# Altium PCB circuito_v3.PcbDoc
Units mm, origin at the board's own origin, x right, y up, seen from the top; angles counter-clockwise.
Board outline 66.93 x 40.77 mm, 2 copper layers (Top Layer, Bottom Layer); 47 components, 32 nets, 112 pads, 55 vias.
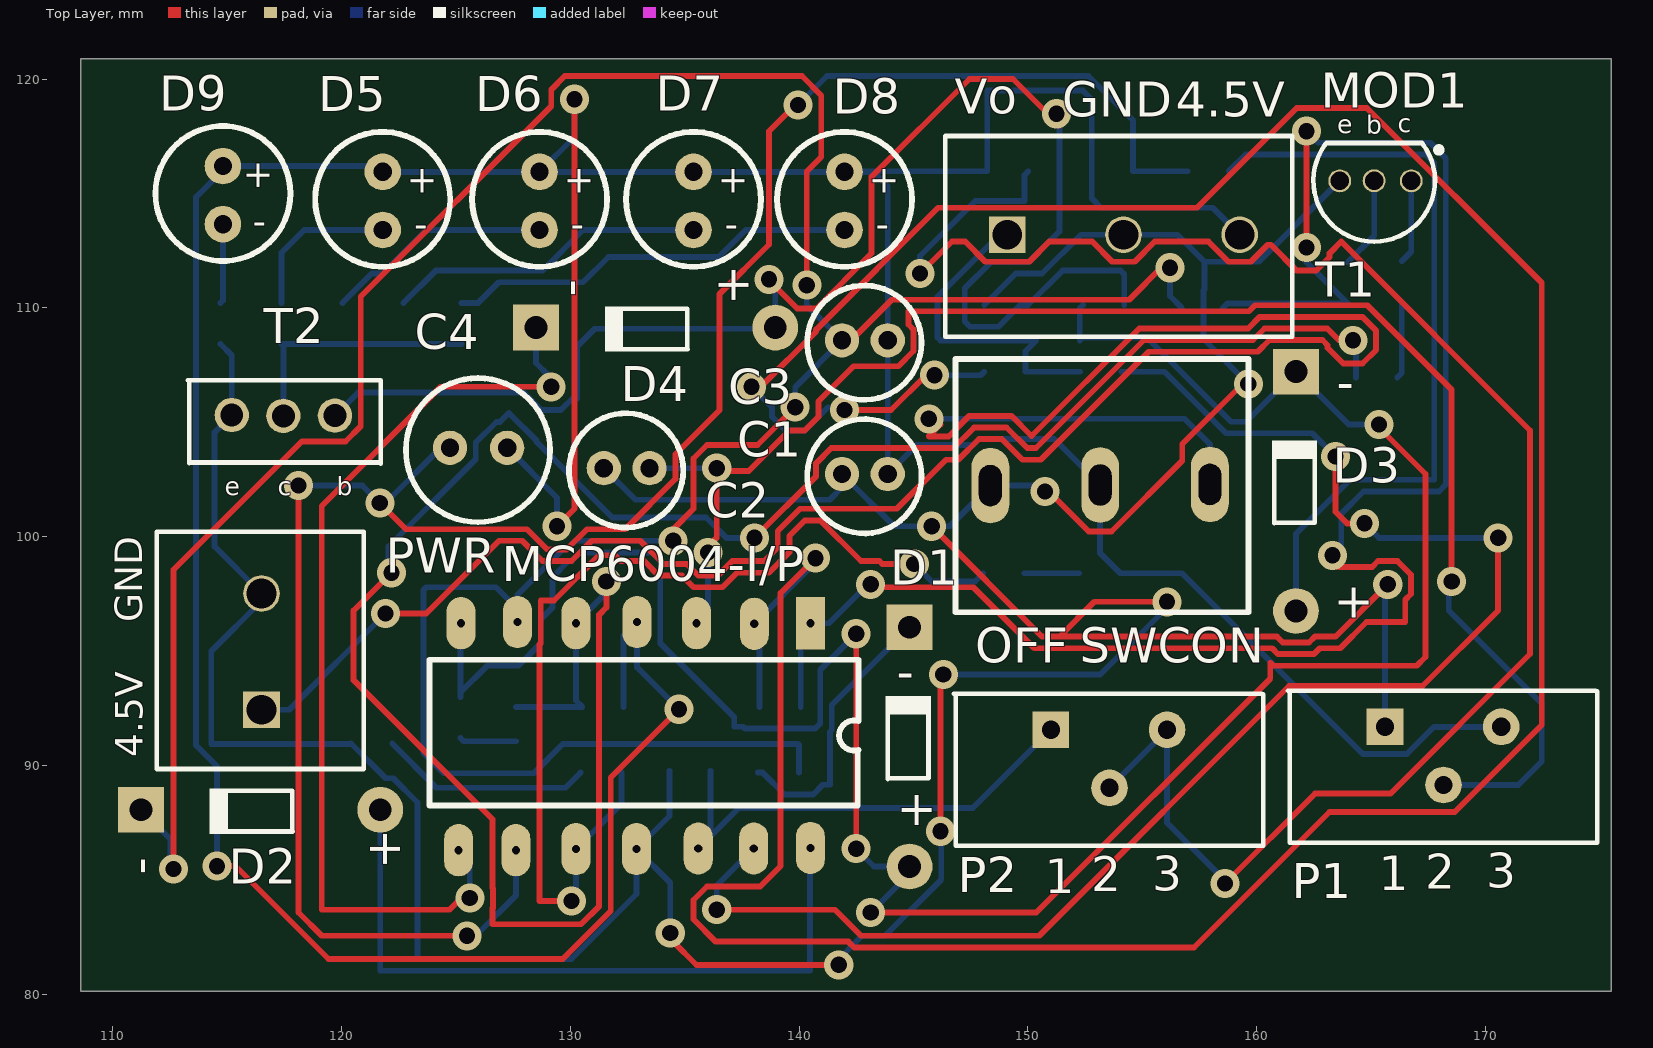
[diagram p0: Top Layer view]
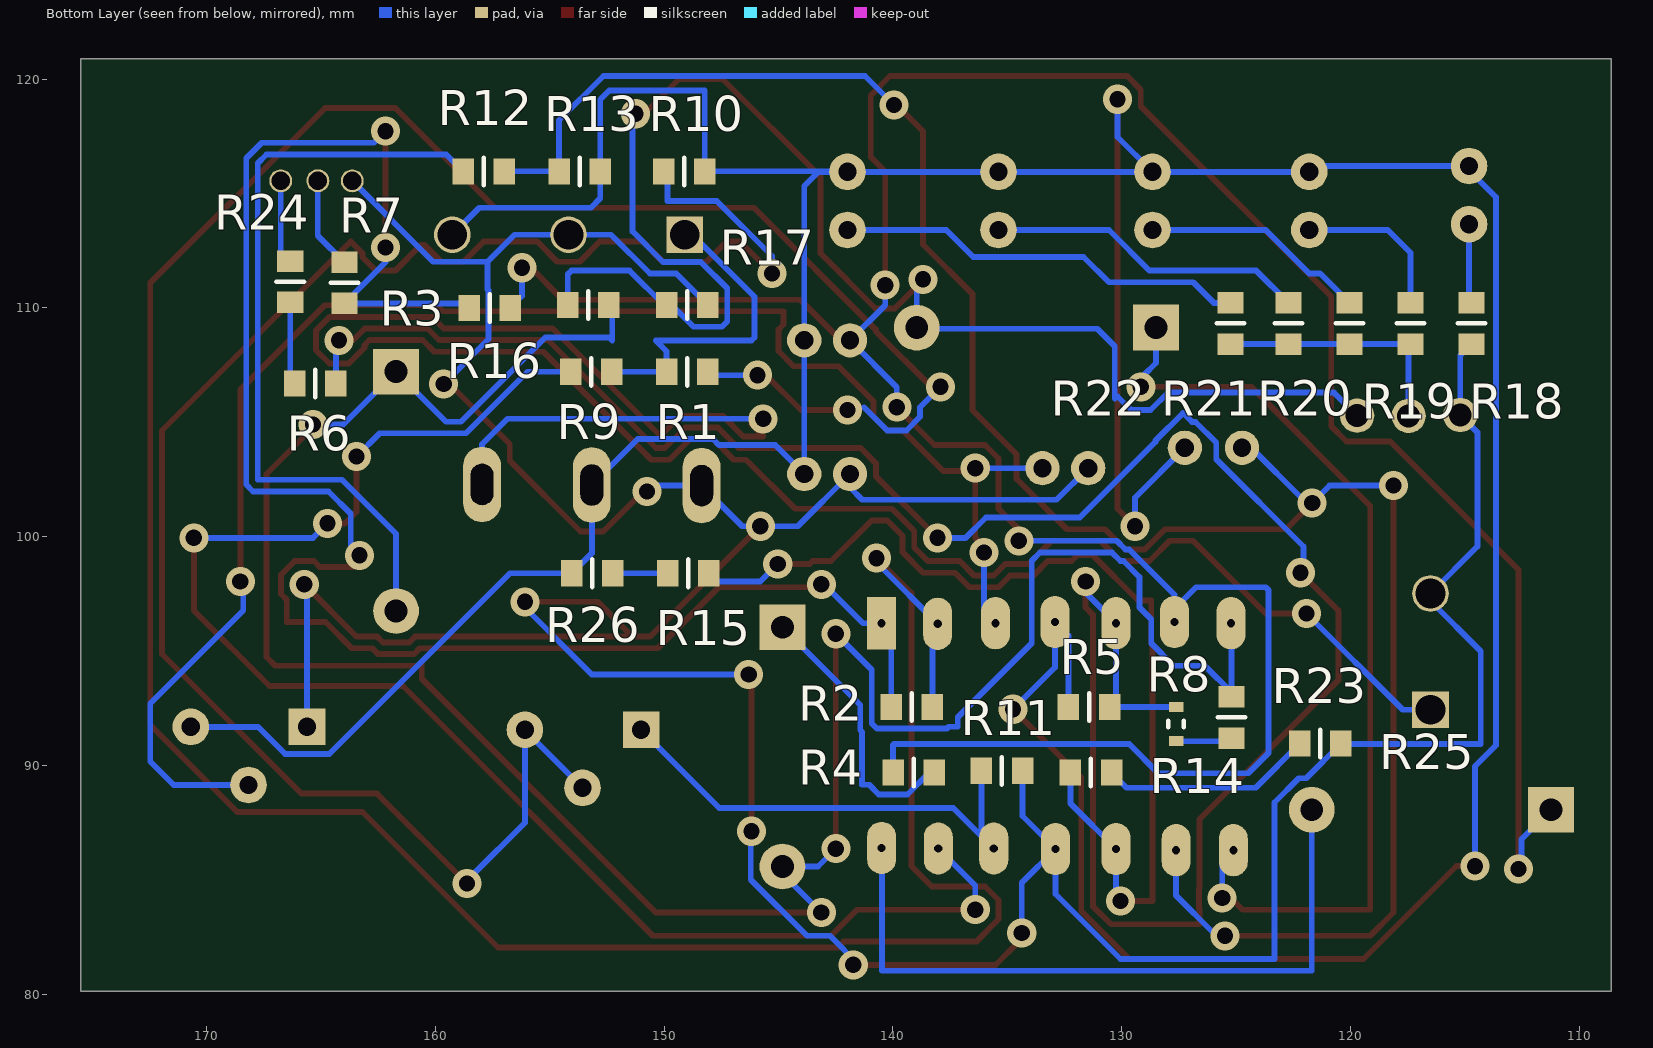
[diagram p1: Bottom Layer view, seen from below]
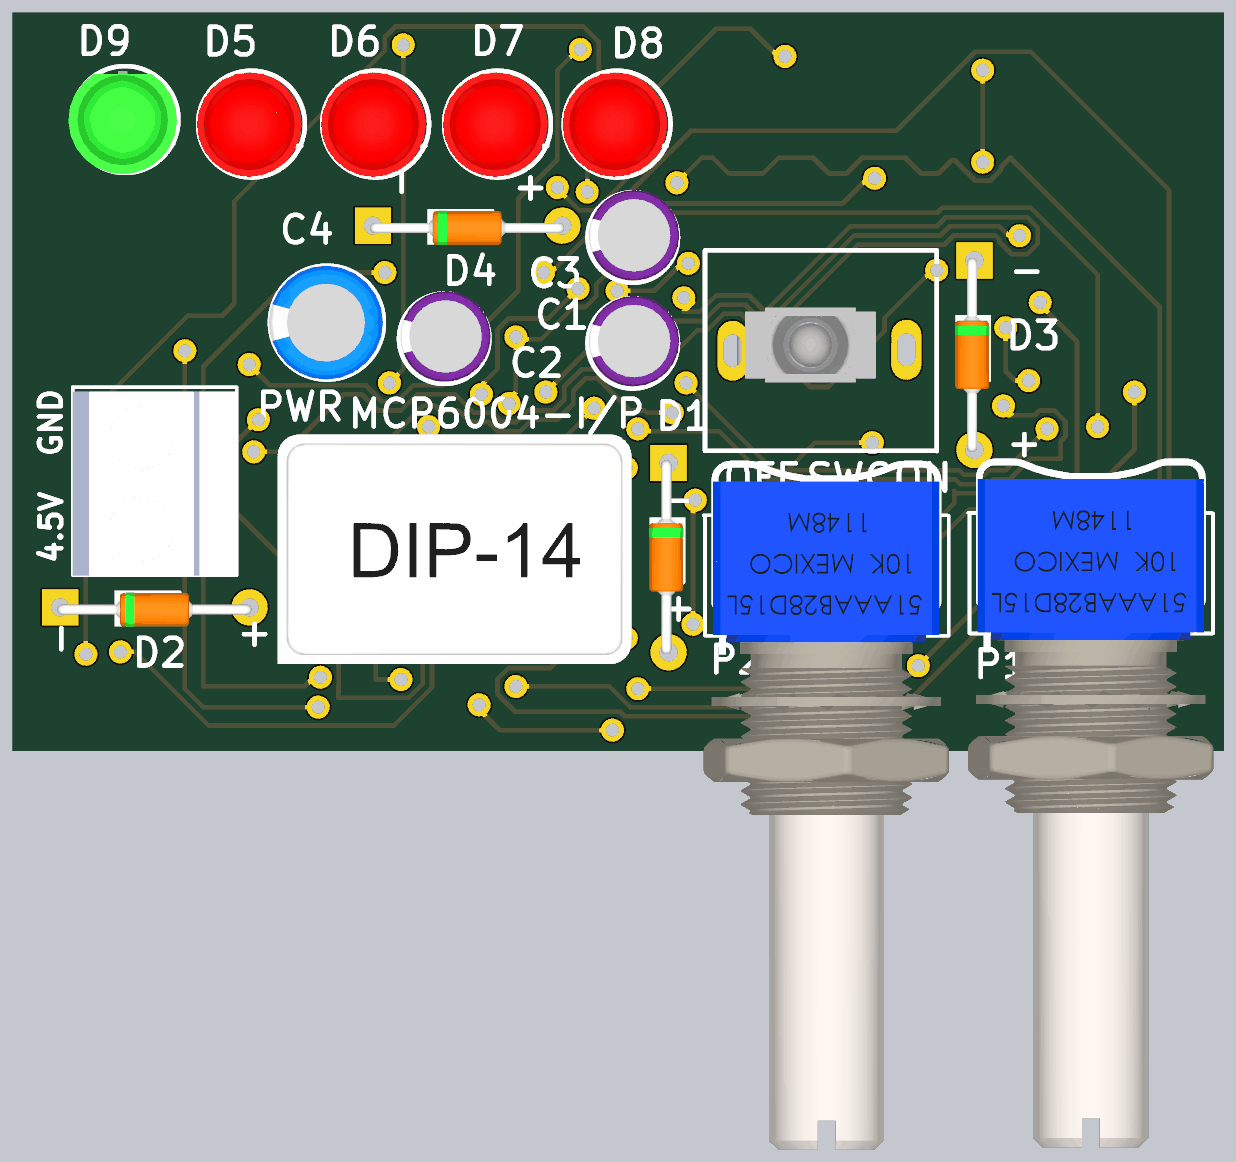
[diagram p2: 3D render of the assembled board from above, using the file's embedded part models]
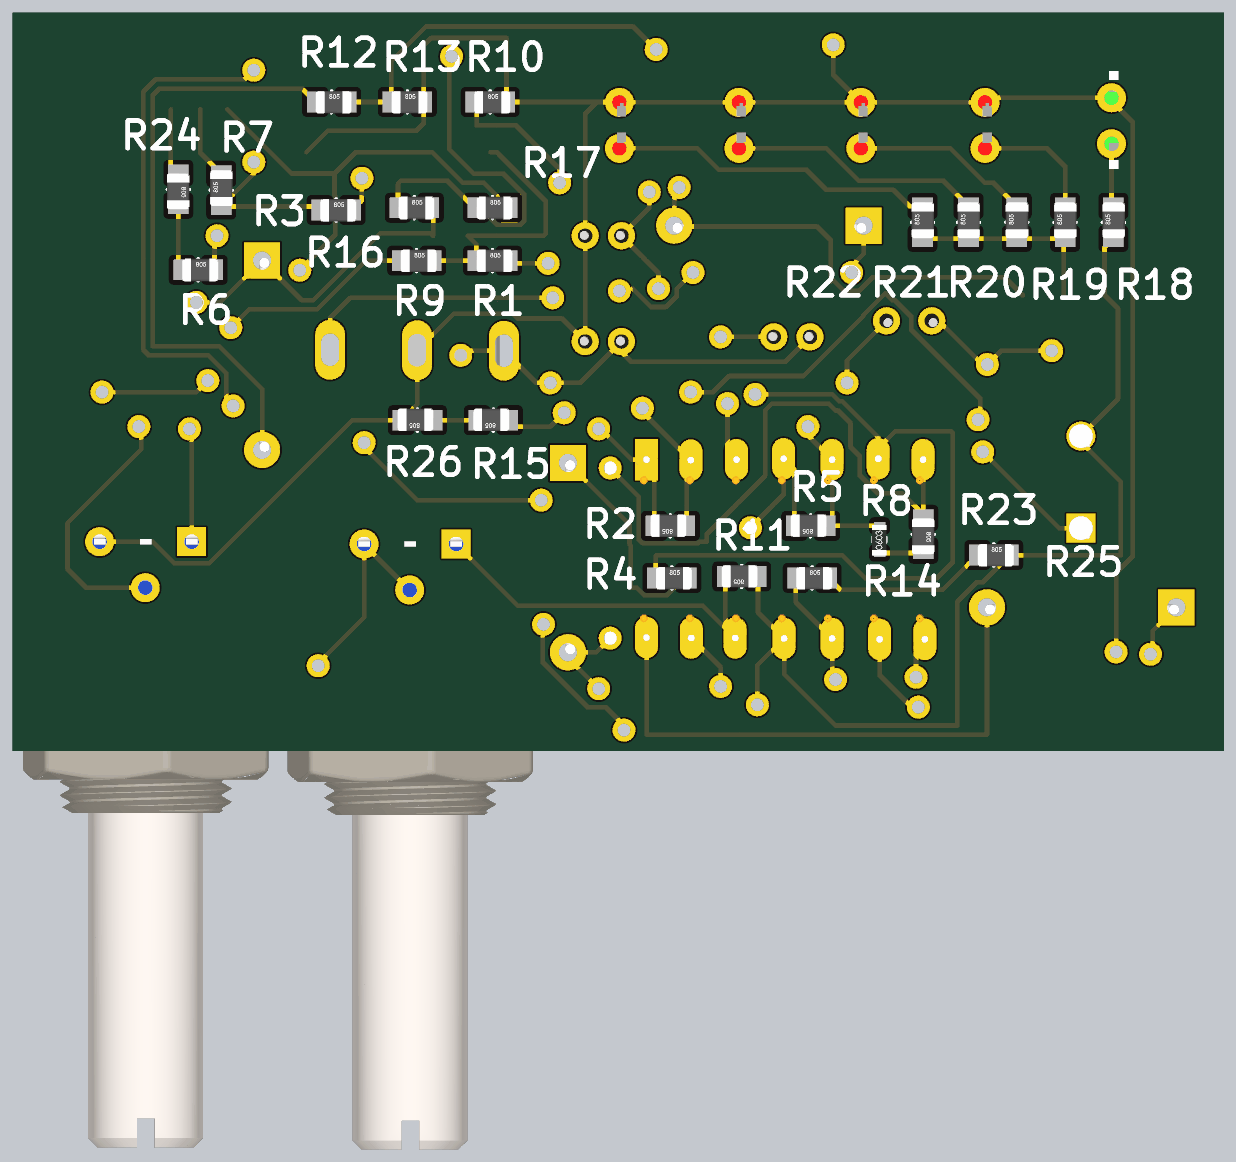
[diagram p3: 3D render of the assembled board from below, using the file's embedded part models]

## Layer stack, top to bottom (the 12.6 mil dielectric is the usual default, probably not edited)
Top Layer: signal copper 0.0356
Dielectric: dielectric 0.32, FR-4, Dk 4.8
Bottom Layer: signal copper 0.0356

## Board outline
108.585,80.137 175.514,80.137 175.514,120.904 108.585,120.904

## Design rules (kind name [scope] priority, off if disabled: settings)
Clearance Clearance_Vias_a_Mano [IsComponentBody vs IsVia] p1: gap=1.524
Clearance [All] p2: gap=0.254
MinimumSolderMaskSliver SilkscreenOverComponentPads [All] p2: minsoldermaskwidth=0.254
PolygonConnect [All] p1: connectstyle=Relief reliefconductorwidth=0.254 reliefentries=4 polygonreliefangle="90 Angle" airgapwidth=0.254
RoutingLayers RoutingLayers_1 [InNet('GND')] p1: top layer_v5=FALSE bottom layer_v5=FALSE
RoutingLayers [All] p2: top layer_v5=TRUE bottom layer_v5=TRUE
RoutingPriority RoutingPriority_GND [InNet('GND')] p1: routingpriority=0
RoutingPriority [All] p2: routingpriority=100
RoutingVias RoutingVias_A_Mano [All] p1: holewidth=0.889 width=2.032 viastyle="Through Hole" minholewidth=0.889 minwidth=1.778 maxholewidth=0.889 maxwidth=2.54
SolderMaskExpansion [All] p1: expansion=0.102
Width Width_Vcc [(InNet('VCC+') AND InNet('VCC-'))] p1: maxlimit=5.08 minlimit=1.778 preferedwidth=2.032
Width [All] p2: maxlimit=2.54 minlimit=0.254 preferedwidth=0.508
26 further rules are at their usual default settings.

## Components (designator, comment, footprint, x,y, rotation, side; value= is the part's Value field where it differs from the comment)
C1 "Cap" "Condensador 5mm" 142.875,102.743 r0 top
C2 "Cap" "Condensador 5mm" 132.461,102.997 r0 top
C3 "Cap" "Condensador 5mm" 142.875,108.585 r0 top
C4 "Cap" "Condensador 6.3mm" 125.984,103.886 r0 top
D1 "BAT85" BAT85 144.78,90.932 r0 top
D2 "Diode BAT18" BAT85 116.332,88.011 r90 top
D3 "Diode BAT18" BAT85 161.671,102.108 r0 top
D4 "Diode BAT18" BAT85 133.604,109.093 r90 top
D5 "LED" LED 121.793,115.951 r270 top
D6 "LED" LED 128.651,115.951 r270 top
D7 "LED" LED 135.382,115.951 r270 top
D8 "LED" LED 141.986,115.951 r270 top
D9 "LED" "LED verde" 114.808,116.205 r270 top
MCP6004-I/P "MCP6004-I/P" MCP6004 139.065,96.393 r270 top
MOD1 "Conector" Conector 185.293,104.394 r270 top
P1 "Res Tap" POTENCIOMETRO 168.148,91.694 r270 top
P2 "Res Tap" POTENCIOMETRO 153.543,91.567 r270 top
PWR "Header 2" ALM 133.096,105.918 r90 top
R1 "Res1" "SMD 0805" 155.956,109.347 r180 bottom
R2 "Res1" "SMD 0805" 132.207,90.424 r0 bottom
R3 "Res1" "SMD 0805" 164.592,112.141 r180 bottom
R4 "Res1" "SMD 0805" 146.05,91.821 r180 bottom
R5 "Res1" "SMD 0805" 124.46,90.424 r0 bottom
R6 "Res1" "SMD 0805" 172.212,108.839 r180 bottom
R7 "Res1" "SMD 0805" 166.116,104.14 r90 bottom
R8 "Res1" "SMD 0603" 127.635,91.821 r180 bottom
R9 "Res1" "SMD 0805" 160.147,109.347 r180 bottom
R10 "Res1" "SMD 0805" 156.083,118.11 r180 bottom
R11 "Res1" "SMD 0805" 128.27,87.63 r0 bottom
R12 "Res1" "SMD 0805" 164.846,118.11 r180 bottom
R13 "Res1" "SMD 0805" 160.655,118.11 r180 bottom
R14 "Res1" "SMD 0805" 138.303,91.821 r180 bottom
R15 "Res1" "SMD 0805" 141.986,96.266 r0 bottom
R16 "Res1" "SMD 0805" 160.274,112.268 r180 bottom
R17 "Res1" "SMD 0805" 155.956,112.268 r180 bottom
R18 "Res3" "SMD 0805" 116.84,102.362 r90 bottom
R19 "Res3" "SMD 0805" 119.507,102.362 r90 bottom
R20 "Res3" "SMD 0805" 122.174,102.362 r90 bottom
R21 "Res3" "SMD 0805" 124.841,102.362 r90 bottom
R22 "Res3" "SMD 0805" 127.381,102.362 r90 bottom
R23 "Res1" "SMD 0805" 123.063,99.06 r270 bottom
R24 "Resistencia" "SMD 0805" 164.211,118.11 r270 bottom
R25 "Resistencia" "SMD 0805" 128.27,93.091 r180 bottom
R26 "Resistencia" "SMD 0805" 146.177,96.266 r0 bottom
SWC "Switch" switch 150.368,101.6 r0 top
T1 "2N3904" "T1 BC550C" 154.813,175.133 r90 top
T2 "QNPN" "T2 BD139" 108.204,40.894 r270 top

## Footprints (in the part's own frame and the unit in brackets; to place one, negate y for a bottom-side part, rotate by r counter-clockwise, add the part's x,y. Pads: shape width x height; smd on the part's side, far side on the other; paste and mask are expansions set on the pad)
ALM [mm]
  rect 1.6x1.6 hole 1.3: 1(-13.48,16.6)
  round 1.6 hole 1.3: 2(-8.4,16.6)
  silkscreen extent -16.07,12.12 -5.7,21.17, body extent -16.1,12.18 -4.94,21.17, height 15.2
BAT85 [mm]
  round 2 hole 1: 1(0.049,-5.353)
  rect 2x2 hole 1: 2(0.049,5.107)
  silkscreen extent -1,-1.53 0.97,2.1, body extent -1.02,-5.46 0.88,5.26, height 1.95
"Condensador 5mm" [mm]
  round 1.5 hole 0.8: 1(-1,0) 2(1,0)
  silkscreen extent -2.52,-2.6 2.47,2.4, body extent -2.45,-2.47 2.55,2.52, height 11
"Condensador 6.3mm" [mm]
  round 1.5 hole 0.8: 1(-1.25,0) 2(1.25,0)
  silkscreen extent -3.17,-3.25 3.12,3.05, body extent -3.22,-3.25 3.08,3.05, height 11.5
Conector [mm]
  rect 1.6x1.6 hole 1.3: 1(-8.811,-36.193)
  round 1.6 hole 1.3: 2(-8.811,-31.113) 3(-8.811,-26.033)
  silkscreen extent -13.13,-38.9 -4.35,-23.72, body extent -13.25,-38.87 -4.25,-23.63, height 15.2
LED [mm]
  round 1.6 hole 0.8: 1(0,0) 2(2.54,0)
  silkscreen extent -1.75,-2.95 4.15,2.95, body extent -1.68,-3.03 4.12,2.77, height 17.5
"LED verde" [mm]
  round 1.6 hole 0.8: 1(0,0) 2(2.54,0)
  silkscreen extent -1.75,-2.95 4.15,2.95, body extent -1.47,-3.12 4.23,2.87, height 20.86
MCP6004 [mm]
  rect 2.286x1.27 hole 0.356: 1(0.175,1.425)
  oval 2.286x1.27 hole 0.356: 2(0.2,-1.025) 3(0.175,-3.55) 4(0.125,-6.15) 5(0.175,-8.825) 6(0.125,-11.375) 7(0.175,-13.85) 8(10.1,-13.95) 9(10.1,-11.45) 10(10.05,-8.825) 11(10.05,-6.175) 12(10.025,-3.475) 13(10.025,-1.05) 14(10,1.425)
  silkscreen extent 1.78,-15.22 8.15,3.52, body extent -1.22,-15.84 11.48,3.72, height 4.61
POTENCIOMETRO [mm]
  rect 1.6x1.6 hole 0.8: 1(0.008,-2.535)
  round 1.6 hole 0.8: 2(2.548,0.025) 3(0.008,2.545)
  silkscreen extent -1.58,-6.78 5.07,6.75, body extent -4.59,-6.77 33.45,6.77, height 14.1
"SMD 0603" [mm]
  rect 0.64x0.44 smd mask+0.26: 1(0.018,-0.76) 2(0.018,0.74)
  silkscreen extent -0.33,-0.15 0.35,0.13, body extent -0.4,-0.9 0.4,0.8, height 0.56
"SMD 0805" [mm]
  rect 0.94x1.14 smd mask+0.26: 1(6.062,-2.136) 2(7.862,-2.136)
  silkscreen extent 6.96,-2.74 6.96,-1.54, body extent 6.08,-2.77 8.08,-1.52, height 0.78
switch [mil]
  oval 65x130 hole 39.37 slot 70.87 at 90 deg: 1(-79,25) 2(109.96,26) 3(298.94,27)
  silkscreen extent -139,-193 365,243, body extent -69,-61 250,136, height 720
"T1 BC550C" [mm]
  round 1 hole 0.8: 1(-59.575,-11.95) 2(-59.571,-10.328) 3(-59.575,-8.825)
  silkscreen extent -62.23,-13.28 -57.92,-7.67, body extent -61.73,-12.63 -58.1,-7.87, height 4.92
"T2 BD139" [mm]
  round 1.5 hole 1: 1(-64.425,6.992) 2(-64.389,9.246) 3(-64.4,11.5)
  silkscreen extent -65.95,5.07 -62.3,13.5, body extent -65.4,5.4 -62.7,13.2, height 13.6

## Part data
C1 C2 C3 C4: "Capacitor"
D1: library part "Diode BAT18", "Low-Loss RF Switching Diode"
D2 D3 D4: "Low-Loss RF Switching Diode"
D5 D6 D7 D8 D9: library part LED2, "Typical RED, GREEN, YELLOW, AMBER GaAs LED"
MCP6004-I/P: "DIP Switch, 7 Position, SPST"
MOD1: library part "Header 3", "Header, 3-Pin"
P1 P2: "Tapped Resistor"
PWR: "Header, 2-Pin"
R1 R2 R3 R4 R5 R6 R7 R8 R9 R10 R11 R12 R13 R14 R15 R16 R17 R18 R19 R20 R21 R22 R23 R24 R25 R26: "Resistor"
SWC: library part Conmutador
T1: "NPN General Purpose Amplifier"
T2: "NPN Bipolar Transistor"

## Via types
v1: diameter 1.27, hole 0.711, Top Layer to Bottom Layer, 55 vias

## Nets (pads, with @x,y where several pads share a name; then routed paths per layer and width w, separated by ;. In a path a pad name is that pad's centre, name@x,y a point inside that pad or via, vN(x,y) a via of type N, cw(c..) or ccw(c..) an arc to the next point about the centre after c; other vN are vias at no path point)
"4.5 V": C1.2 C3.2 C4.2 D5.1 D6.1 D7.1 D8.1 D9.1 MCP6004-I/P.4 MOD1.3 P1.3 R5.2 R10.2 R13.2 R26.2 SWC.2 | length 200.1
  Top Layer w0.254: v1@114.427,85.598 v1(114.554,85.598) 115.36,85.598 119.424,81.534 129.663,81.534 131.764,83.635 131.764,89.473 v1(134.747,92.456) ; v1(129.413,100.457) 130.175,101.219 v1(130.175,119.126)
  Bottom Layer w0.254: v1(114.554,85.598) 114.554,89.96 113.627,90.887 113.627,114.846 114.808,116.027 D9.1 121.539,116.205 D5.1 D6.1 ; C4.2 129.413,101.707 v1(129.413,100.457) ; v1(130.175,119.126) 130.175,117.475 D6.1 ; R5.2 132.322,95.675 MCP6004-I/P.4 132.915,94.288 v1@134.493,92.71 ; MOD1.3 158.079,114.386 153.203,114.386 152.793,114.796 R13.2 152.793,119.114 152.4,119.507 148.221,119.507 R10.2 142.009,115.974 D8.1 ; P1.3 167.752,91.686 166.571,90.505 164.638,90.505 156.741,98.402 R26.2 153.161,99.28 SWC.2 151.154,104.267 147.862,104.267 147.608,104.013 145.145,104.013 C1.2 C3.2 143.875,115.332 143.256,115.951 D8.1 ; D6.1 D7.1 D8.1
GND: C1.1 C2.1 MCP6004-I/P.11 MOD1.2 P1.1 PWR.2 R11.1 R17.2 R18.1 R25.2 SWC.1 T1.3 T2.1 | length 185.9
  Top Layer w0.254: v1@134.493,82.296 135.509,81.28 v1(141.732,81.28) ; v1(145.796,100.457) 150.622,95.631 151.384,95.631 ; v1@146.05,86.741 146.177,86.868 v1(146.177,87.122) v1@146.177,93.853 ; v1(150.749,101.981) 150.909,101.981 152.661,100.228 153.661,100.228 156.754,103.322 156.754,104.049 v1@159.385,106.68 ; v1(156.083,97.155) 152.908,97.155 151.384,95.631 ; v1(165.735,97.917) 163.449,95.631 162.549,95.631 162.292,95.374 161.148,95.374 160.891,95.631 151.384,95.631
  Bottom Layer w0.254: R18.1 115.196,107.932 T2.1 114.446,104.569 114.446,99.568 PWR.2 116.496,97.192 114.3,94.996 114.3,90.932 120.385,90.932 R25.2 121.922,89.441 122.257,89.441 123.317,88.381 123.317,81.534 130.048,81.534 132.89,84.376 MCP6004-I/P.11 ; C2.1 132.842,101.616 141.335,101.616 141.875,102.156 C1.1 144.161,100.457 v1(145.796,100.457) 146.583,100.457 SWC.1 150.368,102.235 v1@150.495,102.108 ; R11.1 134.332,87.785 MCP6004-I/P.11 ; v1(134.366,82.677) 134.366,84.867 MCP6004-I/P.11 ; v1@141.478,81.28 142.748,82.55 143.753,82.55 146.21,85.007 146.21,87.089 v1(146.177,87.122) ; v1(146.304,93.98) 153.162,93.98 156.083,96.901 v1(156.083,97.155) ; R17.2 149.468,111.506 150.622,111.506 152.321,113.205 MOD1.2 156.543,113.205 157.724,112.024 ; v1(159.639,106.68) 157.679,108.64 157.679,110.778 157.724,110.823 157.724,112.024 ; T1.3 160.104,112.024 157.724,112.024 ; P1.1 v1@165.613,97.404
NetD1_3: D1.2 R4.2 | length 12.1
  Bottom Layer w0.254: R4.2 138.409,89.685 139.36,88.734 140.616,88.734 141.036,89.154 141.351,89.154 141.351,91.468 141.428,91.545 141.428,92.638 D1.2
NetD2_1: D2.1 MCP6004-I/P.14 | length 31.2
  Bottom Layer w0.254: D2.1 121.685,81.026 140.481,81.026 140.481,86.384 MCP6004-I/P.14
NetD3_1: D3.1 R12.1 | length 33.7
  Bottom Layer w0.254: R12.1 159.523,116.713 167.386,116.713 167.767,116.332 167.767,102.489 164.084,102.489 161.72,100.125 D3.1
NetD4_1: D4.1 R16.1 R17.1 T2.3 | length 65.7
  Top Layer w0.254: v1(138.684,111.252) 138.684,111.212 139.914,109.982 140.756,109.982 143.167,112.393 143.167,115.735 147.447,120.015 149.352,120.015 v1@151.384,117.983
  Bottom Layer w0.254: T2.3 120.709,106.299 127.976,106.299 128.738,105.537 129.58,105.537 130.175,106.132 130.215,106.132 130.302,106.045 130.302,108.331 131.064,109.093 138.908,109.093 D4.1 138.957,110.725 v1@138.684,110.998 ; 151.384,117.856 151.384,113.35 150.048,112.014 148.397,112.014 147.243,110.86 147.243,109.404 147.466,109.181 148.722,109.181 149.673,110.132 R17.1 150.01,110.132 151.511,111.633 154.051,111.633 154.212,111.472 R16.1
  other v1: 151.257,118.491
NetD5_2: D5.2 R19.2 | length 7
  Bottom Layer w0.254: R19.2 117.371,112.418 118.364,113.411 D5.2
NetD6_2: D6.2 R20.2 | length 9.9
  Bottom Layer w0.254: R20.2 121.32,111.506 121.793,111.506 123.698,113.411 D6.2
NetD7_2: D7.2 R21.2 | length 14
  Bottom Layer w0.254: R21.2 124.114,111.633 128.778,111.633 130.556,113.411 D7.2
NetD8_2: D8.2 R22.2 | length 18.1
  Bottom Layer w0.254: R22.2 125.972,110.224 126.873,111.125 130.556,111.125 131.661,112.23 136.487,112.23 137.668,113.411 D8.2
NetD9_2: D9.2 R18.2 | length 3.5
  Bottom Layer w0.254: R18.2 114.808,110.328 D9.2
NetMOD1_1: MOD1.1 R1.1 R9.2 | length 14.3
  Bottom Layer w0.254: MOD1.1 148.765,113.205 146.05,110.49 146.05,108.712 146.177,108.585 150.368,108.585 149.894,108.111 R1.1 R9.2
NetP2_1: P2.2 P2.3 R10.1 | length 79.7
  Top Layer w0.254: v1(145.288,111.506) 146.685,112.903 147.263,112.903 148.142,112.024 150.058,112.024 150.937,112.903 152.812,112.903 153.691,112.024 154.669,112.024 155.548,112.903 157.892,112.903 158.771,112.024 159.749,112.024 160.487,112.762 160.63,112.762 161.758,111.633 162.6,111.633 163.195,112.228 163.195,112.395 163.703,112.903 171.958,104.648 171.958,94.869 165.862,88.773 162.56,88.773 v1(158.623,84.836)
  Bottom Layer w0.254: v1(145.288,111.506) 145.288,112.268 147.701,114.681 149.86,114.681 149.86,115.813 R10.1 ; P2.2 P2.3@156.088,91.539 ; P2.3 P2.3@156.088,91.539 ; v1@158.369,85.217 156.088,87.498 P2.3@156.088,91.539
NetPWR_1: PWR.1 SWC.3 | length 98.1
  Top Layer w0.254: v1(121.92,96.647) 123.699,96.647 126.874,99.822 127.893,99.822 128.782,98.933 130.044,98.933 130.933,99.822 133.056,99.822 134.072,98.806 135.088,98.806 135.596,98.298 136.438,98.298 137.073,98.933 138.47,98.933 139.065,99.528 139.065,100.247 140.037,101.219 144.272,101.219 146.419,103.366 146.961,103.366 147.862,104.267 148.861,104.267 149.762,103.366 150.566,103.366 155.288,108.088 160.054,108.088 160.562,108.596 162.878,108.596 163.101,108.373 163.101,108.258 163.79,107.569 164.632,107.569 165.227,108.164 165.227,109.006 164.621,109.612 160.141,109.612 159.633,109.104 154.868,109.104 150.164,104.401 149.282,105.283 147.441,105.283 146.54,104.382 145.681,104.382 145.669,104.394 v1@146.177,104.902
  Bottom Layer w0.254: PWR.1 117.711,92.438 v1(121.92,96.647) ; v1(145.669,105.156) 156.845,105.156 157.961,104.04 SWC.3
NetR6_1: R6.1 R24.2 | length 3.4
  Bottom Layer w0.254: R6.1@166.15,106.957 166.347,107.154 R24.2
NetR7_2: R7.2 T1.2 | length 4
  Bottom Layer w0.254: R7.2 165.141,113.163 T1.2
NetR8_1: R8.1 R23.2 | length 2.5
  Bottom Layer w0.254: R23.2 125.336,91.061 R8.1
NetR14_2: R14.2 R25.1 | length 9.3
  Bottom Layer w0.254: R25.1 124.136,89.027 129.783,89.027 R14.2
NetR15_2: R15.2 R26.1 | length 2.4
  Bottom Layer w0.254: R15.2 R26.1
NetR19_1: R19.1 R20.1 R21.1 R22.1 T2.2 | length 11
  Bottom Layer w0.254: T2.2 117.45,108.345 R19.1 R20.1 R21.1 R22.1
NetR24_1: R24.1 T1.1 | length 3.7
  Bottom Layer w0.254: R24.1 166.763,112.464 T1.1
VA+: C2.2 MCP6004-I/P.3 P1.2 | length 70.1
  Top Layer w0.254: v1@136.144,99.695 136.398,99.949 v1(136.398,102.997) 136.525,102.87 137.795,102.87 139.573,104.648 140.248,104.648 140.843,105.243 140.843,105.918 142.379,107.454 144.343,107.454 145.006,108.117 145.006,109.053 144.78,109.279 144.78,109.855 159.666,109.855 159.931,110.12 164.835,110.12 168.529,106.426 v1(168.529,98.044)
  Bottom Layer w0.254: C2.2 v1@136.017,102.997 ; MCP6004-I/P.3 136.017,96.72 v1(136.017,99.314) ; P1.2 171.442,89.146 172.466,90.17 172.466,92.71 168.402,96.774 v1@168.402,97.79
VA-: MCP6004-I/P.2 R1.2 R2.1 | length 141.7
  Top Layer w0.254: v1(137.922,106.553) 138.321,106.553 140.744,108.976 140.744,109.053 146.077,114.386 157.399,114.386 161.758,118.745 164.822,118.745 172.466,111.101 172.466,91.769 168.662,87.965 163.189,87.965 157.266,82.042 142.407,82.042 142.153,82.296 136.358,82.296 135.382,83.272 135.382,84.114 135.977,84.709 138.301,84.709 139.192,85.6 139.192,97.536 v1(140.716,99.06) ; v1(141.986,105.537) 144.018,105.537 v1@145.542,107.061
  Bottom Layer w0.254: v1(137.922,106.553) 138.811,105.664 138.811,105.243 139.406,104.648 140.248,104.648 141.264,105.664 ; R2.1 138.269,95.964 MCP6004-I/P.2 140.589,98.742 v1@140.589,98.806 ; v1(145.923,107.061) 147.944,107.061 R1.2
VB+: MCP6004-I/P.5 R5.1 R6.2 R8.2 | length 101.5
  Top Layer w0.254: v1(122.174,98.425) 120.523,96.774 120.523,93.726 126.599,87.65 126.599,84.642 126.619,84.622 126.619,83.78 126.599,83.76 126.599,83.058 130.469,83.058 131.256,83.845 131.256,96.585 131.572,96.901 v1(131.572,98.044) ; v1(138.049,99.949) 140.744,102.644 140.744,103.211 141.407,103.874 146.75,103.874 147.651,104.775 149.072,104.775 149.973,103.874 150.356,103.874 155.078,108.596 159.844,108.596 160.352,109.104 163.088,109.104 163.596,108.596 164.2,108.596 v1(164.211,108.585)
  Bottom Layer w0.254: 122.047,99.06 122.047,99.568 125.865,103.386 125.865,104.116 126.766,105.017 126.916,105.017 127.309,105.41 128.524,104.195 128.524,104.14 131.826,100.838 135.93,100.838 136.819,99.949 v1(138.049,99.949) ; R8.2 130.521,92.561 130.24,92.842 MCP6004-I/P.5 131.572,97.55 v1(131.572,98.044) ; v1(164.211,108.585) 164.35,108.446 R6.2@164.35,106.957
VB-: C3.1 D2.2 MCP6004-I/P.6 R3.2 R4.1 | length 139.6
  Top Layer w0.254: v1(112.649,85.471) 112.649,98.552 118.26,104.163 120.172,104.163 120.835,104.826 120.835,110.497 129.159,118.821 129.159,119.547 129.754,120.142 140.121,120.142 140.97,119.293 140.97,116.605 140.335,115.97 v1(140.335,110.998) ; v1(134.493,99.822) 134.493,100.33 135.382,101.219 135.382,103.418 135.977,104.013 138.176,104.013 v1(139.827,105.664) ; C3.1 142.276,108.585 144.054,110.363 154.432,110.363 v1@155.956,111.887
  Bottom Layer w0.254: D2.2 112.522,86.763 v1@112.522,85.344 ; v1(134.493,99.822) 130.215,99.822 129.834,99.441 129.667,99.441 127.69,97.464 MCP6004-I/P.6 127.69,96.846 126.746,97.79 123.698,97.79 123.571,97.663 123.571,90.551 124.46,89.662 128.397,89.662 129.667,90.932 139.954,90.932 139.988,90.898 R4.1 ; v1(139.827,105.664) 139.827,106.537 C3.1 140.335,110.125 v1(140.335,110.998) ; v1(156.21,111.76) 156.21,110.525 R3.2
VC+: MCP6004-I/P.10 R14.1 R15.1 | length 44.7
  Top Layer w0.254: v1(130.048,84.074) 128.651,84.074 128.651,95.284 128.706,95.339 128.706,97.21 129.287,97.21 131.264,99.187 131.941,99.187 132.195,98.933 133.227,98.933 133.862,98.298 134.878,98.298 135.386,97.79 136.648,97.79 137.283,98.425 138.68,98.425 139.573,99.318 139.573,100.036 140.248,100.711 140.926,100.711 142.704,98.933 143.51,98.933 143.637,98.806 v1(145.034,98.806)
  Bottom Layer w0.254: v1(130.048,84.074) 130.24,84.266 MCP6004-I/P.10 132.241,88.344 R14.1 ; v1(145.034,98.806) 145.796,98.044 147.69,98.044 R15.1
VC-: C4.1 MCP6004-I/P.9 R12.2 R13.1 | length 92.3
  Top Layer w0.254: v1(118.11,102.235) 118.11,83.566 119.126,82.55 v1(125.476,82.55) ; v1(121.666,101.473) 122.809,100.33 128.103,100.33 128.992,99.441 129.834,99.441 130.723,100.33 132.393,100.33 134.592,102.529 134.592,103.604 136.525,105.537 136.525,110.617 138.684,112.776 138.684,117.729 v1@139.7,118.745
  Bottom Layer w0.254: v1(118.11,102.235) 120.904,102.235 v1(121.666,101.473) ; v1@121.92,101.6 122.047,101.6 124.333,103.886 C4.1 ; v1@125.984,82.677 127.615,84.308 MCP6004-I/P.9 ; v1(139.954,118.872) 141.224,120.142 152.654,120.142 154.593,118.203 R13.1 R12.2
VD+: MCP6004-I/P.12 P2.1 R11.2 | length 20.4
  Bottom Layer w0.254: MCP6004-I/P.12 MCP6004-I/P.12@136.132,86.91 ; R11.2 MCP6004-I/P.12@136.132,86.91 ; P2.1 147.587,88.138 137.36,88.138 MCP6004-I/P.12@136.132,86.91
VD-: MCP6004-I/P.13 R9.1 | length 67.9
  Top Layer w0.254: v1(136.398,83.693) 141.565,83.693 142.708,82.55 150.495,82.55 161.417,93.472 167.259,93.472 170.561,96.774 v1(170.561,99.949) ; v1(163.449,103.505) 163.449,101.092 163.957,100.584 v1(164.719,100.584)
  Bottom Layer w0.254: v1(136.398,83.693) 136.398,84.751 MCP6004-I/P.13 ; R9.1 155.977,107.211 158.667,104.521 162.433,104.521 v1(163.449,103.505) ; v1(164.719,100.584) 165.354,99.949 v1(170.561,99.949)
VOUTA: MCP6004-I/P.1 R2.2 R3.1 R7.1 | length 79.5
  Top Layer w0.254: v1(143.129,97.917) 143.256,97.79 147.618,97.79 150.285,95.123 160.681,95.123 160.938,94.866 162.502,94.866 162.759,95.123 163.659,95.123 164.802,96.266 166.497,96.266 166.497,97.242 166.751,97.496 166.751,98.338 166.156,98.933 165.314,98.933 165.06,98.679 163.576,98.679 v1@163.703,98.806 ; v1(162.179,112.649) v1(162.179,117.729)
  Bottom Layer w0.254: R2.2 140.069,95.797 MCP6004-I/P.1 141.303,96.218 v1@142.748,97.663 ; R3.1 158.727,110.202 R7.1 162.179,112.003 v1(162.179,112.649) ; v1(162.179,117.729) 162.687,117.221 167.596,117.221 168.275,116.542 168.275,102.279 167.977,101.981 164.679,101.981 163.703,101.005 163.703,99.568 v1(163.322,99.187)
VOUTB: D1.1 D3.2 MCP6004-I/P.7 R16.2 R23.1 | length 105.9
  Top Layer w0.254: v1(142.494,86.36) v1(142.494,95.758) v1@142.621,95.885 ; v1(143.129,83.566) 150.368,83.566 160.597,93.795 160.597,94.488 160.727,94.358 167.002,94.358 167.386,94.742 167.386,102.743 v1@165.481,104.648
  Bottom Layer w0.254: R23.1 R23.1@125.199,93.195 ; MCP6004-I/P.7 125.199,96.202 R23.1@125.199,93.195 ; v1(142.494,86.36) 143.275,85.579 D1.1 144.829,85.266 v1@143.383,83.82 ; v1(142.494,95.758) 140.92,94.184 140.92,91.832 140.697,91.609 137.641,91.609 137.556,91.694 137.16,91.694 137.16,92.11 133.931,95.339 133.931,98.947 133.564,99.314 130.425,99.314 130.044,98.933 129.921,98.933 129.224,98.236 129.224,96.911 128.706,96.393 128.706,95.339 127.728,94.361 126.365,94.361 R23.1@125.199,93.195 ; R16.2 152.273,109.993 152.273,108.585 152.4,108.712 155.194,108.712 158.877,105.029 159.534,105.029 D3.2 164.033,104.902 v1(165.354,104.902)
VOUTC: D4.2 MCP6004-I/P.8 | length 40.6
  Top Layer w0.254: v1@125.095,84.074 124.714,83.693 119.126,83.693 119.126,101.346 124.333,106.553 v1(129.159,106.553)
  Bottom Layer w0.254: MCP6004-I/P.8 125.603,85.805 v1(125.603,84.201) ; D4.2 128.497,107.596 v1@129.032,107.061

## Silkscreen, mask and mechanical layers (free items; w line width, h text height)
Mechanical 16:
  drawing of 1877 lines, arcs and shapes, not listed
  text "1" at 36.246,189.611 h1.78
  text "2" at 108.89,189.611 h1.78
  text "3" at 182.042,189.611 h1.78
  text "4" at 254.94,189.611 h1.78
  text "A" at 1.905,166.599 h1.78
  text "A" at 288.925,166.599 h1.78
  text "B" at 1.905,118.542 h1.78
  text "B" at 288.925,118.542 h1.78
  text "C" at 1.905,70.028 h1.78
  text "ENGINEER:" at 173.99,33.02 h1.14
  text "TITLE:" at 212.09,33.02 h1.14
  text "Oscar R. Adamuz Hinojosa" at 175.514,29.464 h1.78
  text "PCB DESIGNER:" at 173.99,25.527 h1.14
  text "Presence Detector" at 218.186,25.4 h5
  text "D" at 1.905,22.022 h1.78
  text "D" at 288.925,22.022 h1.78
  text "Oscar R. Adamuz Hinojosa" at 174.879,21.59 h1.78
  text "DATE:" at 173.99,17.78 h1.14
  text "PART NO.:" at 212.09,17.78 h1.14
  text "REV:" at 265.43,17.78 h1.14
  text "Altium Limited" at 140.97,15.24 h1.78
  text "Bottom Layer" at 222.885,14.986 h1.78
  text "17/12/2014" at 175.26,14.732 h1.78
  text "12a Rodborough Rd" at 140.97,12.7 h1.78
  text "Frenchs Forest" at 140.97,10.16 h1.78
  text "FILE NAME:" at 173.99,10.16 h1.14
  text "DWG NO:" at 212.09,10.16 h1.14
  text "SCALE:" at 265.43,10.16 h1.14
  text "NSW 2086" at 140.97,7.62 h1.78
  text "Circuito V.3" at 175.26,7.112 h1.78
  text "1:1" at 266.954,7.112 h1.78
  text "1" at 36.246,1.651 h1.78
  text "2" at 108.89,1.651 h1.78
  text "3" at 182.042,1.651 h1.78
  text "4" at 254.94,1.651 h1.78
